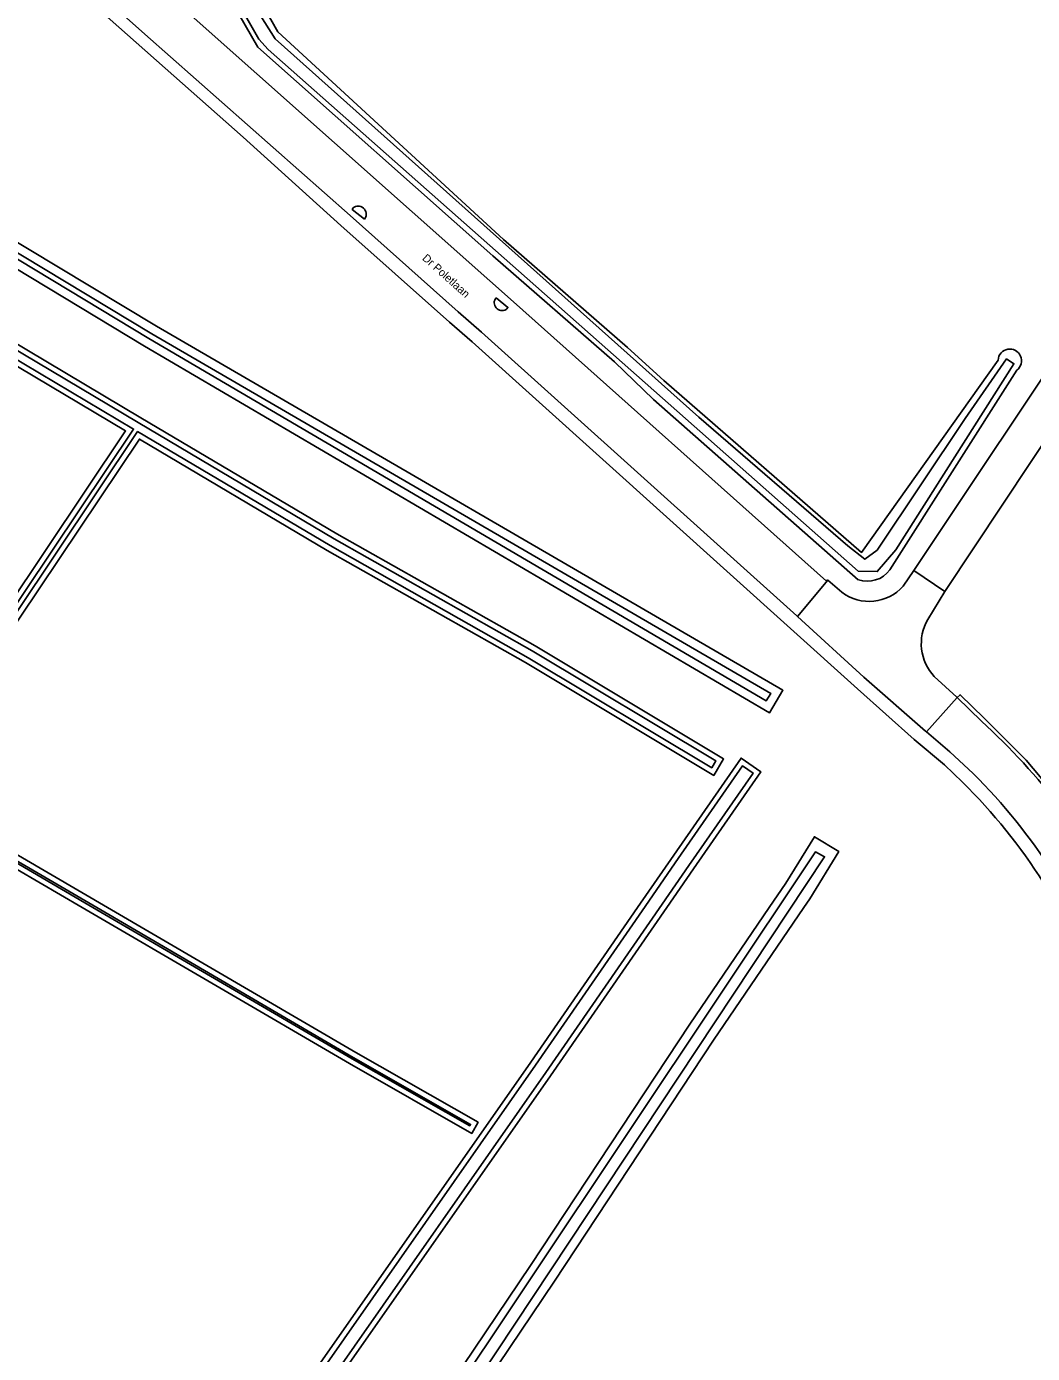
# Model space of a CAD drawing. Extents: x 158132 to 159658, y 385257 to 387209.
# Drawn here: x 159317.9 to 159443.6, y 385694.3 to 385860.1 of the extents above; entities that cross this region are included whole.
import ezdxf

# ---------------------------------------------------------------- set-up
doc = ezdxf.new("R2010")
doc.units = 0
for name, color, linetype in [('IMGEO_Berm_groen', 7, 'Continuous'), ('IMGEO_Fietspad_open', 7, 'Continuous'), ('IMGEO_Gemengd_bos', 7, 'Continuous'), ('IMGEO_Loofbos', 7, 'Continuous'), ('IMGEO_Openbare_ruimte_label', 7, 'Continuous'), ('IMGEO_Rijbaan_lokaal_gesloten', 7, 'Continuous'), ('IMGEO_Rijbaan_lokaal_open', 7, 'Continuous'), ('IMGEO_Waterloop', 7, 'Continuous')]:
    doc.layers.add(name, color=color, linetype=linetype)

msp = doc.modelspace()

# ---------------------------------------------------------------- linework, layer by layer
at = {"layer": 'IMGEO_Berm_groen'}
msp.add_lwpolyline([(159434.2, 385776.23), (159434.55, 385776.59), (159437.58, 385773.66), (159442.83, 385768.4), (159447.61, 385762.72), (159451.89, 385756.65), (159455.64, 385750.23), (159462.24, 385737.74), (159464.56, 385733), (159467.27, 385728.48), (159470.34, 385724.19), (159474.37, 385719.23), (159478.79, 385714.62), (159483.55, 385710.37), (159487.49, 385707.61), (159491.21, 385705.35), (159492.21, 385704.82), (159492.86, 385704.47), (159499.92, 385700.37), (159505.66, 385697.66)], dxfattribs=at)
at = {"layer": 'IMGEO_Fietspad_open'}
msp.add_lwpolyline([(159434.84, 385765.65), (159432.59, 385767.85), (159428.81, 385771), (159421.75, 385777.33), (159373.58, 385820.69), (159370.76, 385823.15), (159357.19, 385835.22), (159344.98, 385846.27), (159299.79, 385886.27), (159298.65, 385887.27), (159299.53, 385888.62)], dxfattribs=at)
msp.add_arc((159388.26, 385717.77), 66.8, 31.9147, 45.7833, dxfattribs=at)
at = {"layer": 'IMGEO_Gemengd_bos'}
for points in [[(159334.13, 385822.64), (159309.84, 385837.27), (159295.23, 385845.59), (159274.78, 385857.06), (159273.36, 385854.53), (159293.81, 385843.06), (159308.4, 385834.75), (159332.64, 385820.16), (159410.74, 385774.32), (159412.41, 385777.16), (159334.13, 385822.64)], [(159311.98, 385778.7), (159332.01, 385808.54), (159355.48, 385794.62), (159380.24, 385780.6), (159403.77, 385766.51), (159405, 385768.56), (159381.45, 385782.68), (159356.68, 385796.7), (159332.2, 385811.21), (159308.61, 385825.24)], [(159307.38, 385823.18), (159330.28, 385809.56), (159310.31, 385779.8)], [(159356.19, 385690.09), (159383.38, 385728.98), (159397.9, 385750), (159401.24, 385754.83), (159409.66, 385766.97), (159407.2, 385768.68), (159398.77, 385756.54), (159394.25, 385750), (159380.91, 385730.69), (159353.73, 385691.8)], [(159305.89, 385761.08), (159324.86, 385750), (159358.26, 385730.49), (159373.55, 385721.77), (159374.34, 385723.16), (159359.06, 385731.88), (159328.03, 385750), (159306.74, 385762.43)], [(159364.2, 385674.09), (159383.86, 385703.31), (159403.74, 385733.43), (159415.03, 385750), (159415.78, 385751.1), (159419.39, 385756.98), (159416.36, 385758.84), (159412.79, 385753.03), (159410.72, 385750), (159400.79, 385735.41), (159380.9, 385705.28), (159361.23, 385676.05)]]:
    msp.add_lwpolyline(points, dxfattribs=at)
at = {"layer": 'IMGEO_Loofbos'}
for points in [[(159334.32, 385885.93), (159349.29, 385859.41), (159377.52, 385833.49)], [(159421.84, 385790.96), (159396.24, 385813.5), (159391.38, 385818.18), (159376.18, 385831.42), (159346.82, 385857.51), (159332.05, 385883.18)], [(159377.52, 385833.49), (159392.98, 385819.98), (159397.53, 385815.84), (159422.24, 385794.37), (159439.3, 385818.41)], [(159441.66, 385817.15), (159425.76, 385792.19)]]:
    msp.add_lwpolyline(points, dxfattribs=at)
for centre, radius, start, end in [((159440.77, 385818.32), 1.47, 307.2302, 176.4963), ((159422.98, 385794.21), 3.44, 250.7531, 324.0265)]:
    msp.add_arc(centre, radius, start, end, dxfattribs=at)
at = {"layer": 'IMGEO_Rijbaan_lokaal_gesloten'}
for points in [[(159432.64, 385789.49), (159472.26, 385849.15), (159475.4, 385853.85), (159491.83, 385878.48), (159500, 385890.93), (159506.1, 385900.24), (159506.91, 385901.32)], [(159428.76, 385792.11), (159471.78, 385856.54), (159487.71, 385880.54), (159500, 385899.39), (159500.64, 385900.37)], [(159414.24, 385786.36), (159414.14, 385786.45), (159374.77, 385821.88), (159371.86, 385824.45), (159358.33, 385836.48), (159332.7, 385859.13), (159312.23, 385877.33)], [(159321.2, 385876.76), (159336.97, 385862.82), (159375.8, 385828.33), (159378.77, 385825.67), (159417.87, 385790.77), (159418.01, 385790.94), (159418.04, 385790.91)], [(159360.12, 385836.02), (159360.27, 385836.21), (159360.3, 385836.29), (159360.34, 385836.43), (159360.36, 385836.6), (159360.35, 385836.78), (159360.31, 385836.96), (159360.23, 385837.12), (159360.14, 385837.27), (159360.01, 385837.4), (159359.86, 385837.5), (159359.7, 385837.58), (159359.53, 385837.63), (159359.35, 385837.64), (159359.18, 385837.63), (159359, 385837.58), (159358.83, 385837.51), (159358.72, 385837.43), (159358.61, 385837.23), (159360.12, 385836.02)], [(159376.59, 385826.2), (159376.46, 385826.01), (159376.41, 385825.89), (159376.36, 385825.73), (159376.35, 385825.56), (159376.37, 385825.39), (159376.41, 385825.22), (159376.49, 385825.07), (159376.58, 385824.93), (159376.71, 385824.81), (159376.85, 385824.71), (159377.01, 385824.65), (159377.17, 385824.6), (159377.34, 385824.59), (159377.51, 385824.61), (159377.68, 385824.66), (159377.83, 385824.74), (159377.93, 385824.81), (159378.06, 385824.98), (159376.59, 385826.2)], [(159434.2, 385776.23), (159437.24, 385773.29)], [(159430.35, 385771.96), (159433.27, 385769.44), (159436.18, 385766.75)]]:
    msp.add_lwpolyline(points, dxfattribs=at)
for centre, radius, start, end in [((159378.59, 385709.49), 86.66, 27.8686, 47.4123), ((159385.95, 385716.04), 71.37, 32.4563, 45.2722)]:
    msp.add_arc(centre, radius, start, end, dxfattribs=at)
at = {"layer": 'IMGEO_Rijbaan_lokaal_open'}
for points in [[(159427.46, 385790.16), (159428.76, 385792.11)], [(159428.76, 385792.11), (159432.64, 385789.49)], [(159418.04, 385790.91), (159414.24, 385786.36)], [(159418.04, 385790.91), (159419.79, 385789.39)], [(159432.64, 385789.49), (159430.53, 385785.98)], [(159414.24, 385786.36), (159422.54, 385778.77), (159430.24, 385772.05), (159430.35, 385771.96)], [(159431.33, 385778.87), (159434.16, 385776.27), (159434.2, 385776.23)], [(159430.35, 385771.96), (159434.2, 385776.23)]]:
    msp.add_lwpolyline(points, dxfattribs=at)
for centre, radius, start, end in [((159423.2, 385793.94), 5.69, 233.0715, 318.4251), ((159435.71, 385782.97), 6, 149.8126, 223.1116)]:
    msp.add_arc(centre, radius, start, end, dxfattribs=at)
at = {"layer": 'IMGEO_Waterloop'}
for points in [[(159344.54, 385865.62), (159348.96, 385858.57), (159401.91, 385811.27), (159420.54, 385795.2), (159422.65, 385793.51), (159424.21, 385794.66), (159435.19, 385811.1), (159440.37, 385818.55), (159441.29, 385817.95), (159426.51, 385794.68), (159424.21, 385791.97), (159421.84, 385792.05), (159348.12, 385857.23), (159346.93, 385858.51), (159333.43, 385882.16)], [(159274.87, 385854.95), (159275.2, 385855.54), (159294.68, 385844.62), (159309.28, 385836.31), (159333.57, 385821.68), (159410.89, 385776.76), (159410.34, 385775.83), (159333.21, 385821.11), (159308.96, 385835.71), (159294.35, 385844.03), (159274.87, 385854.95)], [(159310.89, 385779.42), (159331.28, 385809.79), (159307.74, 385823.78)], [(159308.25, 385824.64), (159331.84, 385810.61), (159356.33, 385796.09), (159381.1, 385782.07), (159404.04, 385768.32), (159403.53, 385767.47), (159380.6, 385781.21), (159355.83, 385795.23), (159331.79, 385809.48), (159311.39, 385779.09)], [(159354.3, 385691.4), (159381.49, 385730.29), (159394.83, 385749.6), (159399.35, 385756.14), (159407.38, 385767.71), (159408.69, 385766.79), (159400.66, 385755.23), (159397.32, 385750.4), (159382.8, 385729.38), (159355.61, 385690.49)], [(159306.37, 385761.84), (159327.68, 385749.4), (159358.71, 385731.27), (159373.39, 385722.9), (159373.29, 385722.72), (159358.61, 385731.1), (159325.21, 385750.6), (159306.26, 385761.67)], [(159331.07, 385625.71), (159417.63, 385756.34), (159416.5, 385756.96), (159357.31, 385668.29)]]:
    msp.add_lwpolyline(points, dxfattribs=at)

# ---------------------------------------------------------------- texts
at = {"layer": 'IMGEO_Openbare_ruimte_label'}
msp.add_text('Dr Poletlaan', height=1, rotation=318.1619, dxfattribs=at).set_placement((159367.28, 385831.02))

doc.saveas('drawing.dxf')
